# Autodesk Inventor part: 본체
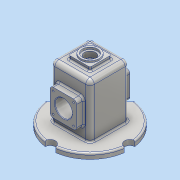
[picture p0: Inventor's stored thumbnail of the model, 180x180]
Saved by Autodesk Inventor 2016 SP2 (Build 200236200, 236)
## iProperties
Created: 2018-07
Part Number: 본체
Material: 알루미늄 6061
Document SubType Name: Modeling
Designer: Administrator
Density: 2.7 g/cm^3
Appearance: 알루미늄 - 평지
Mass: 909.433 g
Surface Area: 1017.53 cm^2
Volume: 336.827 cm^3
Author: Administrator
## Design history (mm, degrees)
sketch "스케치1"
  geometry: C1 r 75 at (0, 0); 1 further point
  constraints: 1 centre point, 1 coincident
  dimensions: "d0" = 150 diameter of C1
extrude "돌출1" new body sketch "스케치1" distance "d1" = 10; taper "d2" = 0 deg
sketch "스케치2"
  geometry: L1 (-37, -37)-(37, -37); L2 (37, -37)-(37, 37); L3 (37, 37)-(-37, 37); L4 (-37, 37)-(-37, -37); L5 (-37, -37)-(37, 37); L6 (37, -37)-(-37, 37); C1 r 75 at (0, 0) reference
  constraints: 12 end point, 2 midpoint, 2 parallel, 1 horizontal, 1 perpendicular
  dimensions: "d3" = 74 distance of L1.start L1.end; "d4" = 74 distance of L1.end L2.end
extrude "돌출2" join sketch "스케치2" distance "d5" = 100; taper "d6" = 0 deg
sketch "스케치3"
  geometry: L1 (-20, -20)-(20, -20); L2 (20, -20)-(20, 20); L3 (20, 20)-(-20, 20); L4 (-20, 20)-(-20, -20); L5 (-20, -20)-(20, 20); L6 (20, -20)-(-20, 20); 1 further point
  constraints: 12 end point, 2 midpoint, 2 parallel, 1 horizontal, 1 perpendicular
  dimensions: "d7" = 40 distance of L1.end L2.end; "d8" = 40 distance of L2.end L3.end
extrude "돌출3" join sketch "스케치3" distance "d9" = 7; taper "d10" = 0 deg
sketch "스케치4"
  geometry: C1 r 17.5 at (0, 0); 1 further point
  constraints: 1 centre point, 1 coincident
  dimensions: "d11" = 35 diameter of C1
extrude "돌출4" join sketch "스케치4" distance "d12" = 3; taper "d13" = 0 deg
sketch "스케치6"
  geometry: L1 (25, 30)-(-25, 30); L2 (-25, 30)-(-25, 80); L3 (-25, 80)-(25, 80); L4 (25, 80)-(25, 30); L5 (25, 30)-(-25, 80); L6 (-25, 30)-(25, 80); L7 (-75, 0)-(75, 0) reference; 4 further points
  constraints: 12 end point, 4 midpoint, 2 parallel, 1 horizontal, 1 perpendicular, 1 vertical alignment
  dimensions: "d16" = 55 distance from line of L7 point (0, 55); "d17" = 50 distance of L2.end L3.end; "d18" = 50 distance of L3.end L1.start
extrude "돌출5" join sketch "스케치6" stored distance "d19" = 100; taper "d20" = 0 deg
sketch "스케치7"
  geometry: L1 (32, 32)-(-32, 32); L2 (-32, 32)-(-32, -32); L3 (-32, -32)-(32, -32); L4 (32, -32)-(32, 32); L5 (32, 32)-(-32, -32); L6 (-32, 32)-(32, -32); C1 r 75 at (0, 0) reference
  constraints: 12 end point, 2 midpoint, 2 parallel, 1 horizontal, 1 perpendicular
  dimensions: "d21" = 64 distance of L2.end L3.end; "d22" = 64 distance of L3.end L1.start
extrude "돌출6" cut sketch "스케치7" distance "d23" = 105; taper "d24" = 0 deg
sketch "스케치9"
  geometry: C1 r 17.5 at (0, 0) reference
hole "구멍1" sketch "스케치9" at (0, 0) diameter "d28" = 21; stored, may be unused: countersink angle "d32" = 90 deg, drill point angle "d34" = 118 deg; dims "d29" = 6, "d30" = 28, "d31" = 4, "d33" = 8
sketch "스케치10"
  geometry: C1 r 10 at (75, 0); 1 further point
  constraints: 1 centre point, 1 horizontal alignment, 1 other
  dimensions: "d35" = 20 diameter of C1
extrude "돌출8" cut sketch "스케치10" stored distance "d36" = 105; taper "d37" = 0 deg
sketch "스케치12"
  geometry: L1 (25, 80)-(-25, 80) reference; L2 (-25, 80)-(-25, 30) reference; C1 r 16 at (0, 55); 3 further points
  constraints: 2 midpoint, 1 centre point, 1 horizontal alignment, 1 vertical alignment
  dimensions: "d45" = 32 diameter of C1
extrude "돌출9" cut sketch "스케치12" stored distance "d46" = 105; taper "d47" = 0 deg
sketch "스케치14"
  geometry: L1 (-50, 80)-(-50, 30) reference; L2 (-50, 55)-(50, 55); L3 (50, 30)-(50, 80) reference; L4 (-32, 80)-(-32, 55); L5 (-32, 55)-(-25, 55); L6 (-25, 55)-(-25, 77.452); L7 (-25, 77.452)-(-32, 80); L8 (-32, 0)-(-32, 105) reference; L9 (0, -24)-(0, 144) reference; L10 (32, 80)-(32, 55); L11 (32, 55)-(25, 55); L12 (25, 55)-(25, 77.452); L13 (25, 77.452)-(32, 80); 1 further point
  constraints: 18 end point, 4 symmetric about line, 2 collinear, 2 midpoint, 2 perpendicular, 1 vertical
  dimensions: "d48" = 7 distance between parallel lines of L4 L6; "d51" = 50 diameter of L4.start L2; "d52" = 110 deg angle of L8 L7
revolve "회전2" sketch "스케치14" stored, may be unused: angle "d53" = 90 deg
sketch "스케치15"
  geometry: C1 r 16 at (0, 0) reference; C2 r 16 at (0, 0); 1 further point
  constraints: 1 centre point, 1 coincident, 1 concentric
extrude "돌출10" cut sketch "스케치15" stored distance "d54" = 105; taper "d55" = 0 deg
fillet "모깎기1" dims "d56" = 3
fillet "모깎기2" dims "d57" = 6
chamfer "모따기1" distance "d58" = 1; stored, may be unused: second distance "d59" = 2, angle "d60" = 45 deg
fillet "모깎기3" dims "d61" = 3
fillet "모깎기4" dims "d62" = 3
fillet "모깎기5" dims "d63" = 8
fillet "모깎기6" dims "d64" = 8
fillet "모깎기7" dims "d65" = 3
fillet "모깎기8" dims "d66" = 3
fillet "모깎기9" dims "d67" = 3
fillet "모깎기10" dims "d68" = 3
sketch "스케치16"
  geometry: A1 r 6 centre (19, 36) between (19, 30) and (25, 36) reference; A2 r 6 centre (19, 74) between (25, 74) and (19, 80) reference; A3 r 6 centre (-19, 74) between (-19, 80) and (-25, 74) reference; A4 r 6 centre (-19, 36) between (-25, 36) and (-19, 30) reference; 1 further point
hole "구멍2" sketch "스케치16" at (19, 74), (19, 36), (-19, 36), (-19, 74) diameter "d69" = 3.242; stored, may be unused: countersink angle "d73" = 90 deg, drill point angle "d75" = 118 deg; dims "d70" = 8, "d71" = 28, "d72" = 4, "d74" = 10
sketch "스케치18"
  geometry: L1 (-8, 89)-(-8, 0) reference; L2 (11.5, -18)-(46.5, -18) reference; 2 further points
  constraints: 1 other
  dimensions: "d80" = 37 distance from line of L1 point (29, 12); "d81" = 30 distance from line of point (29, 12) L2
feature "엠보싱2" sketch "스케치18" dims "d1" = 10, "d82" = 0.5, "d83" = 0
node "솔리드1"
pattern_circular "원형 패턴1" dims angle "d39" = 360 deg
mirror "대칭1"
